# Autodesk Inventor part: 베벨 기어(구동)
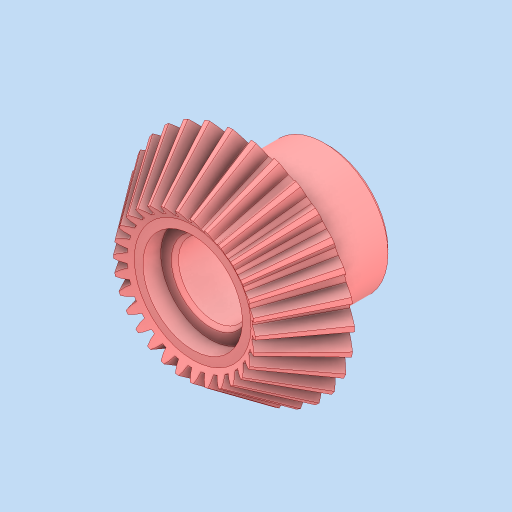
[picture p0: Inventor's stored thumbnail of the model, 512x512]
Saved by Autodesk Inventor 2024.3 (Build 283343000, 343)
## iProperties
Created: 2026-01
Part Number: 베벨 기어(구동)
Material: 강철, 합금
Document SubType Name: Modeling
Designer: PC2-02
Density: 7.73 g/cm^3
Appearance: 기본값
Author: jhkim
Sending System: Autodesk Inventor 2026
Preprocessor: ST-DEVELOPER v20.1
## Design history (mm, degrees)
node "베벨 기어(구동)1"
node "솔리드1"
body "Solid1"
